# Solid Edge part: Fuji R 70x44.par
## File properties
Title: Lines R 70x44
Author: DESYS
Template: Parte SCARABEO.par
Last saved by: i.fialdini
Revision: 31
Application: Solid Edge
Tipo di contenuto documento: 0
Precisione: 0.990
Document Number: 6004
Revision: 0
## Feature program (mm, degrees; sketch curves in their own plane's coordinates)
sketch for "unnamed Protrusion 1" plane through (0, 0, 0) normal (0, -1, 0) x-axis (1, 0, 0)
extrude "unnamed Protrusion 1" add finite 140 along -normal
fillet "Rotondo_22" radius 35
lofted cutout "unnamed LoftedCutout 1"
sketch for "unnamed Protrusion 2" plane through (0, 140, 0) normal (0, 1, 0) x-axis (-1, 0, 0)
extrude "unnamed Protrusion 2" add through along -normal
draft "Spoglia_2"  Angles1 = 5 deg
fillet "Rotondo_46" radius 90
fillet "Rotondo_57" radius 5
fillet "Rotondo_50" radius 20
sketch for "unnamed Cutout 1" plane through (0, 0, 0) normal (0, -1, 0) x-axis (-1, 0, 0)
  line (-265, -195) -> (265, -195)
  arc centre (265, -160) radius 35 from (300, -160) to (265, -195) cw
  line (300, -160) -> (300, 125)
  arc centre (265, 125) radius 35 from (265, 160) to (300, 125) cw
  line (265, 160) -> (-265, 160)
  arc centre (-265, 125) radius 35 from (-300, 125) to (-265, 160) cw
  line (-300, 125) -> (-300, -160)
  arc centre (-265, -160) radius 35 from (-300, -160) to (-265, -195) ccw
extrude "unnamed Cutout 1" cut along +normal
fillet "Rotondo_27" radius 10
sketch for "unnamed Protrusion 3" plane through (0, 22, 0) normal (0, -1, 0) x-axis (1, 0, 0)
extrude "unnamed Protrusion 3" add to key point along +normal
sketch for "Foro_9" plane through (0, 40, 0) normal (0, 1, 0) x-axis (0, 0, -1)
hole "Foro_9" diameter 50 through
sketch for "ProtrusioneEstrusa_8" plane through (0, 0, 0) normal (0, 0, 1) x-axis (1, 0, 0)
extrude "ProtrusioneEstrusa_8" add finite 50 symmetric
fillet "Rotondo_28" radius 10
fillet "Rotondo_29" radius 5
fillet "Rotondo_33" radius 15
fillet "Rotondo_34" radius 5
fillet "Rotondo_35" radius 5
sketch for "unnamed Cutout 2" plane through (0, 67.5, 220) normal (0, 0, 1) x-axis (1, 0, 0)
extrude "unnamed Cutout 2" cut through along -normal
fillet "Rotondo_38" radius 5
sketch for "unnamed Cutout 3" #1 plane through (0, 67.5, 220) normal (0, 0, 1) x-axis (1, 0, 0)
sketch for "unnamed Cutout 3" #2 plane through (0, 67.5, 220) normal (0, 0, 1) x-axis (1, 0, 0)
extrude "unnamed Cutout 3" cut through along -normal
sketch for "Foro_10" plane through (0, 67.5, 220) normal (0, 0, 1) x-axis (1, 0, 0)
  hole centre (-290, -37.5) bore radius 7.5
hole "Foro_10" finite
sketch for "unnamed Hole 1" plane through (0, 67.5, 220) normal (0, 0, 1) x-axis (1, 0, 0)
hole "unnamed Hole 1" finite
pattern "unnamed Pattern 1" of "Foro_10", "unnamed Hole 1"
fillet "Rotondo_39" radius 5
sketch for "Foro_12" plane through (0, 140, 0) normal (0, 1, 0) x-axis (-1, 0, 0)
hole "Foro_12" diameter 36 through
fillet "Rotondo_49" radius 2
fillet "Rotondo_52" radius 10
fillet "Rotondo_53" radius 5
sketch for "unnamed Cutout 4" plane through (0, 0, 0) normal (0, -1, 0) x-axis (1, 0, 0)
extrude "unnamed Cutout 4" cut to key point along -normal
draft "Spoglia_3"  Angles1 = 5 deg
draft "Spoglia_4"  Angles1 = 5 deg
fillet "Rotondo_54" radius 5
mirror "unnamed Mirror 1" of "unnamed Cutout 4", "Spoglia_3", "Rotondo_54", "Spoglia_4" about plane through (0, 0, 0) normal (1, 0, 0)
extrude "unnamed Cutout 5" cut finite 107
draft "unnamed Draft 1"
draft "unnamed Draft 2"
fillet "unnamed Round 1"
Other named dimensions: "SuperficieOffset_2": Distance = 18 mm
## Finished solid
Body 1: sheet body, 10 faces, 29 edges, 22 vertices.
  Faces by surface: blend 6, plane 2, cone 1, offset 1
  Edges by curve: intersection 15, circle 9, line 4, curve on surface 1
Body 2: solid body, 165 faces, 382 edges, 218 vertices.
  Faces by surface: cylinder 64, plane 36, blend 31, torus 26, sphere 4, cone 2, offset 1, spline 1
  Edges by curve: circle 151, line 139, intersection 70, ellipse 20, curve on surface 2
Bounding box of the edges (mm; curved faces can reach further): 700.000 x 140.000 x 430.000, from (-350, 0, -210) to (350, 140, 220).
Cylindrical faces by radius (mm): R5 x36, R7.5 x2, R10 x4, R15 x7, R18 x1, R25 x3, R35 x10, R130.8333 x1
Conical faces (half-angle, radius in mm at the cone's reference point): 5 deg R32.0685 x2, 5 deg R50 x1
Toroidal faces (ring radius, tube radius in mm): R10 r5 x2, R20 r2 x1, R20 r5 x2, R20 r15 x4, R30 r5 x13, R35 r10 x1, R40 r5 x1, R45.4183 r5 x1, R135.8333 r5 x1
Spherical faces by radius (mm): R5 x4
Planar faces by outward normal: +x 2, +y 4, +z 5, -x 2, -y 10, -z 7, oblique 6
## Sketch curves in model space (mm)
arc centre (0, 31.3466, -204.6591) radius 110 from (0, 40, -95) through (0, 108.3537, -126.1103) to (0, 140, -187.5)
arc centre (0, 31.3466, 204.6591) radius 110 from (0, 40, 95) through (0, 108.3537, 126.1103) to (0, 140, 187.5)
ellipse centre (0, 140, 0) radii 220, 187.5
arc centre (-258.2169, -35.8962, 0) radius 180 from (-95, 40, 0) through (-145.7718, 104.6602, 0) to (-220, 140, 0)
arc centre (258.2169, -35.8962, 0) radius 180 from (95, 40, 0) through (145.7718, 104.6602, 0) to (220, 140, 0)
circle centre (0, 40, 0) radius 95
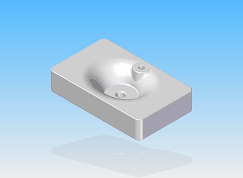
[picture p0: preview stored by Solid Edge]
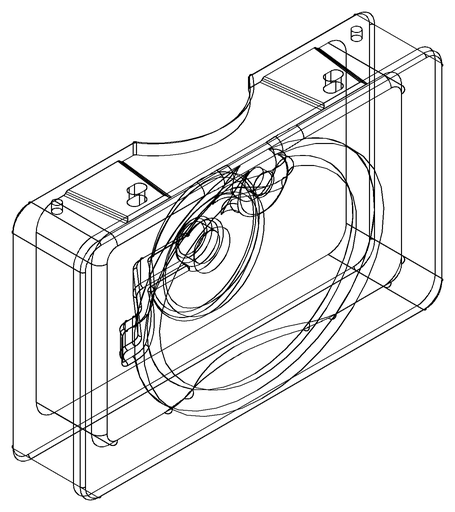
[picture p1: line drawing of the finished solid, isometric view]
